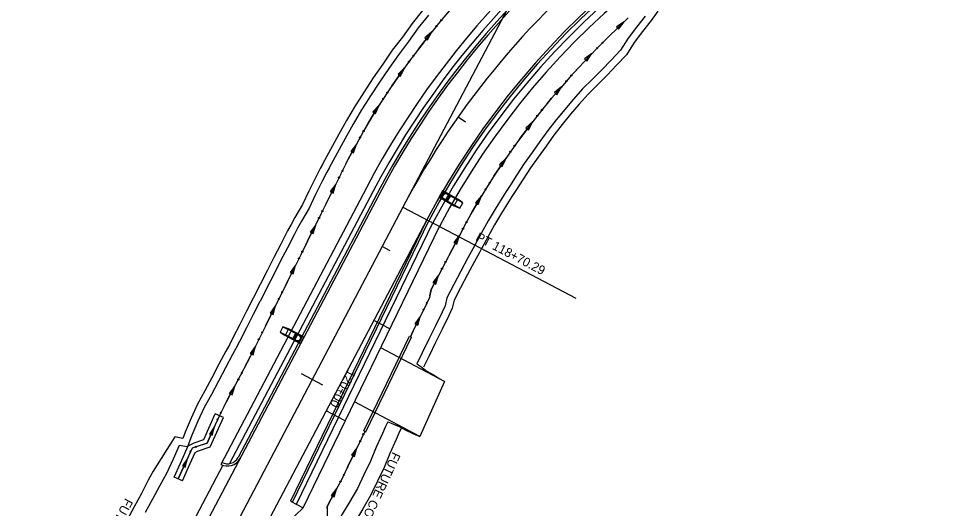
# Model space of a CAD drawing. Extents: x 979959 to 994833, y 1835619 to 1845316.
# Drawn here: x 981201 to 981821, y 1841316 to 1841642 of the extents above; entities that cross this region are included whole.
import ezdxf

# ---------------------------------------------------------------- set-up
doc = ezdxf.new("R2010")
doc.units = 0
for name, color, linetype in [('Future 5 Lane Construction Limits', 7, 'Continuous'), ('R_CONCRETE', 7, 'Continuous'), ('R_Drainage', 7, 'Continuous'), ('R_Horz Alg', 7, 'Continuous'), ('R_Horz Alg Annot', 7, 'Continuous'), ('R_Horz Alg Annot_Side Road', 7, 'Continuous'), ('R_Horz Alg Stationing', 7, 'Continuous'), ('R_Proposed Const Limits', 7, 'Continuous'), ('R_Proposed Road', 7, 'Continuous'), ('R_Special Ditch', 7, 'Continuous')]:
    doc.layers.add(name, color=color, linetype=linetype)

msp = doc.modelspace()

# ---------------------------------------------------------------- linework, layer by layer
at = {"layer": 'Future 5 Lane Construction Limits'}
for points in [[(981469.86, 1841647.75), (981462.95, 1841639.14), (981456.53, 1841630.08), (981449.82, 1841621.29), (981443.46, 1841612.11), (981437.18, 1841602.97), (981431.1, 1841593.69), (981427.88, 1841588.75), (981425.1, 1841584.24), (981419.39, 1841574.68), (981413.98, 1841564.96), (981408.66, 1841555.26), (981403.45, 1841545.52), (981403.29, 1841545.22), (981401.89, 1841542.58), (981398.76, 1841536.53), (981394.3, 1841527.52), (981389.96, 1841518.68), (981385.02, 1841510.12), (981382.41, 1841505.41), (981380.17, 1841501.16), (981375.65, 1841492.23), (981371, 1841483.4), (981366.42, 1841474.47), (981361.88, 1841465.54), (981361.75, 1841465.28), (981357.36, 1841456.61), (981357.25, 1841456.4), (981352.83, 1841447.7), (981348.31, 1841438.79), (981343.77, 1841429.91), (981341.36, 1841425.28), (981339.12, 1841421.19), (981334.29, 1841412.35), (981329.76, 1841403.44), (981324.98, 1841394.75), (981320.05, 1841385.8), (981315.89, 1841376.42), (981311.85, 1841367.11), (981310.28, 1841363.07)], [(981626.6, 1841647.41), (981622.05, 1841641.05), (981616.26, 1841633.71), (981610.88, 1841626.49), (981605.76, 1841618.26), (981599.17, 1841611.33), (981592.86, 1841604.77), (981586.39, 1841598.4), (981580.12, 1841592.15), (981574.3, 1841585.52), (981568.49, 1841578.71), (981562.83, 1841571.84), (981557.42, 1841564.81), (981552.17, 1841557.56), (981546.89, 1841550.27), (981541.71, 1841543.04), (981536.83, 1841535.61), (981532, 1841528.08), (981529.5, 1841524.06), (981527.25, 1841520.44), (981522.45, 1841512.89), (981517.94, 1841505.24), (981513.57, 1841497.48), (981509.32, 1841489.61), (981509.21, 1841489.4), (981507.81, 1841486.74), (981504.55, 1841480.83), (981499.91, 1841472.02), (981495.22, 1841463.2), (981490.94, 1841454.93), (981489.76, 1841449.64), (981487.46, 1841444.88), (981483.1, 1841435.84), (981478.66, 1841426.86), (981474.26, 1841417.9), (981470.68, 1841410.51)], [(981455.78, 1841369.76), (981454.2, 1841366.49), (981452.42, 1841362.24), (981448.28, 1841353.1), (981444.33, 1841343.79), (981439.95, 1841334.52), (981435.42, 1841325.11), (981430.15, 1841316.11), (981425.1, 1841307.51), (981420.98, 1841300.36)], [(981310.28, 1841363.07), (981304.97, 1841364.01), (981290.56, 1841341.24)], [(981290.56, 1841341.24), (981287.4, 1841335.32), (981282.82, 1841326.43), (981278.1, 1841317.62), (981273.33, 1841308.83)]]:
    msp.add_lwpolyline(points, dxfattribs=at)
at = {"layer": 'R_CONCRETE'}
for p, q in [((981337.43, 1841377), (981331.95, 1841379.45)), ((981310.1, 1841334.88), (981304.62, 1841337.34))]:
    msp.add_line(p, q, dxfattribs=at)
for points in [[(981304.62, 1841337.34), (981308.73, 1841346.48), (981313.95, 1841358.11), (981317.83, 1841360.17), (981324.28, 1841362.36), (981331.95, 1841379.45)], [(981310.1, 1841334.88), (981314.2, 1841344.02), (981318.58, 1841353.78), (981320.22, 1841354.65), (981328.68, 1841357.52), (981337.43, 1841377)]]:
    msp.add_lwpolyline(points, dxfattribs=at)
at = {"layer": 'R_Drainage'}
for p, q in [((981483.52, 1841527.9), (981481.03, 1841523.57)), ((981481.9, 1841523.07), (981484.39, 1841527.4)), ((981482.33, 1841522.82), (981484.82, 1841527.15)), ((981482.58, 1841523.25), (981484.58, 1841526.72)), ((981483.52, 1841527.9), (981493.49, 1841522.17)), ((981484.58, 1841526.72), (981493.25, 1841521.74)), ((981481.03, 1841523.57), (981482.33, 1841522.82)), ((981481.9, 1841523.07), (981491, 1841517.84)), ((981482.58, 1841523.25), (981491.25, 1841518.27)), ((981488.73, 1841524.91), (981486.23, 1841520.58)), ((981491.25, 1841518.27), (981493.25, 1841521.74)), ((981496.71, 1841519.74), (981493.25, 1841521.74)), ((981496.71, 1841519.74), (981493.49, 1841522.17)), ((981494.72, 1841516.28), (981496.71, 1841519.74)), ((981491, 1841517.84), (981494.72, 1841516.28)), ((981494.72, 1841516.28), (981491.25, 1841518.27)), ((981377.05, 1841437.28), (981375.19, 1841433.74)), ((981375.19, 1841433.74), (981378.5, 1841431.44)), ((981375.19, 1841433.74), (981378.73, 1841431.88)), ((981380.83, 1841435.86), (981377.05, 1841437.28)), ((981377.05, 1841437.28), (981380.59, 1841435.42)), ((981380.59, 1841435.42), (981378.73, 1841431.88)), ((981389.44, 1841430.76), (981380.59, 1841435.42)), ((981390.11, 1841430.97), (981380.83, 1841435.86)), ((981383.36, 1841428.87), (981385.69, 1841433.3)), ((981388.67, 1841426.08), (981378.49, 1841431.44)), ((981387.58, 1841427.22), (981378.73, 1841431.88)), ((981389.67, 1841431.2), (981387.34, 1841426.78)), ((981389.44, 1841430.76), (981387.58, 1841427.22)), ((981390.11, 1841430.97), (981387.78, 1841426.54)), ((981388.67, 1841426.08), (981391, 1841430.5)), ((981391, 1841430.5), (981389.67, 1841431.2)), ((981430.84, 1841368.02), (981461.27, 1841431.06)), ((981432.19, 1841367.36), (981462.62, 1841430.4)), ((981461.27, 1841431.06), (981462.62, 1841430.4)), ((981430.84, 1841368.02), (981432.19, 1841367.36))]:
    msp.add_line(p, q, dxfattribs=at)
for points in [[(981484.82, 1841527.15), (981482.33, 1841522.82), (981481.03, 1841523.57), (981483.52, 1841527.9)], [(981488.73, 1841524.91), (981486.23, 1841520.58), (981481.9, 1841523.07), (981484.39, 1841527.4)], [(981383.36, 1841428.87), (981385.69, 1841433.3), (981390.11, 1841430.97), (981387.78, 1841426.54)], [(981387.34, 1841426.78), (981389.67, 1841431.2), (981391, 1841430.5), (981388.67, 1841426.08)]]:
    msp.add_lwpolyline(points, close=True, dxfattribs=at)
for centre, radius in [((981485.31, 1841523.99), 2.5), ((981485.31, 1841523.99), 2.5), ((981485.31, 1841523.99), 2), ((981485.31, 1841523.99), 2), ((981386.74, 1841429.92), 2.5), ((981386.74, 1841429.92), 2.5), ((981386.74, 1841429.92), 2), ((981386.74, 1841429.92), 2)]:
    msp.add_circle(centre, radius, dxfattribs=at)
at = {"layer": 'R_Horz Alg'}
msp.add_line((981456.9, 1841516.96), (980717.33, 1840113.21), dxfattribs=at)
msp.add_arc((981939.67, 1841262.61), 545.67, 103.27832, 152.21752, dxfattribs=at)
at = {"layer": 'R_Horz Alg Annot'}
msp.add_lwpolyline([(981456.9, 1841516.96), (981571.91, 1841456.37)], dxfattribs=at)
at = {"layer": 'R_Horz Alg Annot_Side Road'}
msp.add_line((981572.65, 1841736.66), (981456.9, 1841516.96), dxfattribs=at)
at = {"layer": 'R_Horz Alg Stationing'}
for points in [[(981498.48, 1841573.42), (981493.57, 1841576.87)], [(981448.36, 1841487.88), (981443.05, 1841490.68)], [(981403.52, 1841398.48), (981389.36, 1841405.94)]]:
    msp.add_lwpolyline(points, dxfattribs=at)
at = {"layer": 'R_Proposed Const Limits'}
for points in [[(981487.65, 1841647.5), (981480.68, 1841639.14), (981473.86, 1841630.66), (981467.2, 1841622.06), (981460.7, 1841613.34), (981454.36, 1841604.5), (981448.18, 1841595.54), (981442.17, 1841586.48), (981439.06, 1841581.64), (981436.42, 1841577.24), (981430.95, 1841567.84), (981425.66, 1841558.34), (981420.54, 1841548.75), (981415.61, 1841539.08), (981415.46, 1841538.79), (981414.15, 1841536.14), (981411.15, 1841530.09), (981406.71, 1841521.13), (981402.27, 1841512.17), (981397.83, 1841503.2), (981395.48, 1841498.46), (981393.38, 1841494.24), (981388.94, 1841485.28), (981384.5, 1841476.32), (981380.06, 1841467.35), (981375.62, 1841458.39), (981375.49, 1841458.13), (981371.17, 1841449.43), (981371.07, 1841449.21), (981366.73, 1841440.47), (981362.29, 1841431.5), (981357.85, 1841422.54), (981355.5, 1841417.8), (981355.49, 1841417.79), (981353.31, 1841413.63), (981348.65, 1841404.78), (981344, 1841395.93), (981339.34, 1841387.08), (981334.69, 1841378.23), (981330.58, 1841369.09), (981326.48, 1841359.94), (981316.53, 1841356.52), (981307.36, 1841336.11)], [(981473.85, 1841644.74), (981466.95, 1841636.13), (981460.56, 1841627.11), (981453.86, 1841618.34), (981447.58, 1841609.27), (981441.33, 1841600.18), (981435.29, 1841590.96), (981432.1, 1841586.07), (981429.37, 1841581.65), (981423.72, 1841572.18), (981418.36, 1841562.54), (981413.06, 1841552.88), (981407.86, 1841543.16), (981407.71, 1841542.88), (981406.33, 1841540.26), (981403.22, 1841534.27), (981398.78, 1841525.31), (981394.38, 1841516.32), (981389.37, 1841507.66), (981386.81, 1841503.03), (981384.61, 1841498.86), (981380.1, 1841489.94), (981375.44, 1841481.09), (981370.88, 1841472.19), (981366.34, 1841463.28), (981366.21, 1841463.02), (981361.82, 1841454.36), (981361.71, 1841454.14), (981357.29, 1841445.44), (981352.77, 1841436.52), (981348.21, 1841427.61), (981345.77, 1841422.92), (981345.77, 1841422.91), (981343.51, 1841418.79), (981338.72, 1841410.01), (981334.18, 1841401.1), (981329.36, 1841392.34), (981324.53, 1841383.58), (981320.47, 1841374.42), (981316.48, 1841365.21), (981313.46, 1841357.43)], [(981618.05, 1841644.05), (981612.29, 1841636.75), (981606.74, 1841629.31), (981601.78, 1841621.34), (981595.56, 1841614.79), (981589.3, 1841608.28), (981582.88, 1841601.95), (981576.48, 1841595.58), (981570.52, 1841588.79), (981564.66, 1841581.92), (981558.92, 1841574.96), (981553.41, 1841567.81), (981548.12, 1841560.5), (981542.83, 1841553.2), (981537.58, 1841545.87), (981532.63, 1841538.34), (981527.77, 1841530.75), (981525.25, 1841526.7), (981523.01, 1841523.11), (981518.19, 1841515.5), (981513.61, 1841507.74), (981509.19, 1841499.89), (981504.91, 1841491.97), (981504.79, 1841491.73), (981503.41, 1841489.11), (981500.15, 1841483.2), (981495.49, 1841474.35), (981490.8, 1841465.53), (981486.2, 1841456.65), (981485.01, 1841451.29), (981482.96, 1841447.05), (981478.61, 1841438.04), (981474.17, 1841429.07), (981469.77, 1841420.09), (981466.18, 1841412.69)], [(981466.18, 1841412.69), (981468.78, 1841410.8), (981472.88, 1841407.84), (981477.18, 1841405.28), (981481.51, 1841402.77), (981484.58, 1841400.98)], [(981446.77, 1841374.11), (981445.08, 1841370.6), (981445.08, 1841370.59), (981443.25, 1841366.24), (981439.12, 1841357.12), (981435.2, 1841347.88), (981430.92, 1841338.83), (981426.59, 1841329.81), (981421.53, 1841321.17), (981416.45, 1841312.54), (981412.32, 1841305.35)], [(981446.77, 1841374.11), (981449.01, 1841373.27), (981454.85, 1841370.67), (981458.89, 1841368.62), (981463.53, 1841366.35), (981468.17, 1841364.42)], [(981313.46, 1841357.43), (981307.95, 1841358.4), (981303.88, 1841349.25)], [(981303.88, 1841349.25), (981299.71, 1841340.14), (981294.93, 1841331.35), (981290.21, 1841322.54), (981285.41, 1841313.76)]]:
    msp.add_lwpolyline(points, dxfattribs=at)
at = {"layer": 'R_Proposed Road'}
for p, q in [((981440.97, 1841525.35), (980701.4, 1840121.6)), ((981432.57, 1841529.78), (981335.62, 1841345.76)), ((981436.99, 1841527.45), (981341.56, 1841346.31)), ((981439.65, 1841526.05), (981347.12, 1841350.43)), ((981472.82, 1841508.57), (980733.25, 1840104.82)), ((981472.82, 1841508.57), (981382.06, 1841321.29)), ((981383.39, 1841320.59), (981474.15, 1841507.87)), ((981386.04, 1841319.19), (981476.8, 1841506.47)), ((981390.47, 1841316.86), (981481.23, 1841504.14)), ((981448.19, 1841435.98), (981437.53, 1841441.59)), ((981484.58, 1841400.98), (981442.08, 1841423.37)), ((981484.58, 1841400.99), (981468.17, 1841364.42)), ((981468.17, 1841364.42), (981424.63, 1841387.36)), ((981418.52, 1841374.75), (981405.84, 1841381.43)), ((981337, 1841345.16), (980694.33, 1840125.33)), ((981382.06, 1841321.29), (981390.47, 1841316.86)), ((981390.47, 1841316.86), (981371.29, 1841298.7))]:
    msp.add_line(p, q, dxfattribs=at)
for centre, radius, start, end in [((981939.67, 1841262.61), 527.67, 103.27832, 152.21752), ((981939.67, 1841262.61), 526.17, 103.27832, 152.21752), ((981939.67, 1841262.61), 573.17, 117.37429, 152.21752), ((981939.67, 1841262.61), 568.17, 117.37429, 152.21752), ((981939.67, 1841262.61), 523.17, 103.27832, 152.21752), ((981939.67, 1841262.61), 518.17, 103.27832, 152.21752), ((981939.67, 1841262.61), 565.17, 117.37429, 152.21752), ((981939.67, 1841262.61), 563.67, 117.37429, 152.21752), ((981340.04, 1841354.16), 9.5, 242.21752, 332.21752), ((981340.04, 1841354.16), 8, 242.21752, 332.21752)]:
    msp.add_arc(centre, radius, start, end, dxfattribs=at)
at = {"layer": 'R_Special Ditch'}
for p, q in [((981604.07, 1841640.24), (981598.98, 1841636.88)), ((981598.98, 1841636.88), (981600.43, 1841635.35)), ((981600.43, 1841635.35), (981604.07, 1841640.24)), ((981476.15, 1841633.51), (981471.57, 1841629.5)), ((981473.22, 1841628.17), (981476.15, 1841633.51)), ((981471.57, 1841629.5), (981473.22, 1841628.17)), ((981582.72, 1841619.11), (981577.79, 1841615.53)), ((981579.31, 1841614.06), (981582.72, 1841619.11)), ((981577.79, 1841615.53), (981579.31, 1841614.06)), ((981458, 1841609.58), (981453.65, 1841605.32)), ((981455.37, 1841604.09), (981458, 1841609.58)), ((981453.65, 1841605.32), (981455.37, 1841604.09)), ((981562.41, 1841596.99), (981557.7, 1841593.12)), ((981559.3, 1841591.74), (981562.41, 1841596.99)), ((981557.7, 1841593.12), (981559.3, 1841591.74)), ((981441.07, 1841584.77), (981436.94, 1841580.3)), ((981438.72, 1841579.15), (981441.07, 1841584.77)), ((981436.94, 1841580.3), (981438.72, 1841579.15)), ((981543.28, 1841573.83), (981538.78, 1841569.72)), ((981538.78, 1841569.72), (981540.46, 1841568.43)), ((981540.46, 1841568.43), (981543.28, 1841573.83)), ((981425.93, 1841558.84), (981422.17, 1841554.05)), ((981424.03, 1841553.05), (981425.93, 1841558.84)), ((981422.17, 1841554.05), (981424.03, 1841553.05)), ((981525.55, 1841549.59), (981521.28, 1841545.24)), ((981521.28, 1841545.24), (981523.03, 1841544.04)), ((981523.03, 1841544.04), (981525.55, 1841549.59)), ((981412.17, 1841532.14), (981408.56, 1841527.24)), ((981410.45, 1841526.3), (981412.17, 1841532.14)), ((981408.56, 1841527.24), (981410.45, 1841526.3)), ((981509.28, 1841524.34), (981505.26, 1841519.76)), ((981505.26, 1841519.76), (981507.07, 1841518.67)), ((981507.07, 1841518.67), (981509.28, 1841524.34)), ((981398.83, 1841505.23), (981395.22, 1841500.32)), ((981397.11, 1841499.38), (981398.83, 1841505.23)), ((981395.22, 1841500.32), (981397.11, 1841499.38)), ((981494.53, 1841498.18), (981490.82, 1841493.35)), ((981492.69, 1841492.37), (981494.53, 1841498.18)), ((981490.82, 1841493.35), (981492.69, 1841492.37)), ((981385.49, 1841478.31), (981381.88, 1841473.41)), ((981383.77, 1841472.47), (981385.49, 1841478.31)), ((981381.88, 1841473.41), (981383.77, 1841472.47)), ((981480.63, 1841471.56), (981476.91, 1841466.73)), ((981478.79, 1841465.75), (981480.63, 1841471.56)), ((981476.91, 1841466.73), (981478.79, 1841465.75)), ((981372.15, 1841451.4), (981368.54, 1841446.49)), ((981370.43, 1841445.55), (981372.15, 1841451.4)), ((981368.54, 1841446.49), (981370.43, 1841445.55)), ((981468.47, 1841444.24), (981464.91, 1841439.3)), ((981464.91, 1841439.3), (981466.81, 1841438.38)), ((981466.81, 1841438.38), (981468.47, 1841444.24)), ((981358.81, 1841424.49), (981355.2, 1841419.58)), ((981357.1, 1841418.64), (981358.81, 1841424.49)), ((981355.2, 1841419.58), (981357.1, 1841418.64)), ((981344.99, 1841397.82), (981341.26, 1841393)), ((981343.14, 1841392.02), (981344.99, 1841397.82)), ((981341.26, 1841393), (981343.14, 1841392.02)), ((981331.45, 1841371.02), (981328.03, 1841365.98)), ((981329.96, 1841365.11), (981331.45, 1841371.02)), ((981328.03, 1841365.98), (981329.96, 1841365.11)), ((981426.26, 1841356.79), (981422.7, 1841351.85)), ((981422.7, 1841351.85), (981424.6, 1841350.93)), ((981424.6, 1841350.93), (981426.26, 1841356.79)), ((981313.51, 1841349.79), (981310.08, 1841344.75)), ((981312.01, 1841343.89), (981313.51, 1841349.79)), ((981310.08, 1841344.75), (981312.01, 1841343.89)), ((981412.96, 1841329.86), (981409.18, 1841325.08)), ((981411.05, 1841324.08), (981412.96, 1841329.86)), ((981409.18, 1841325.08), (981411.05, 1841324.08))]:
    msp.add_line(p, q, dxfattribs=at)
for points in [[(981606.9, 1841642.91), (981600.17, 1841636.55), (981593.54, 1841630.09), (981587, 1841623.54), (981580.57, 1841616.89), (981574.25, 1841610.16), (981568.02, 1841603.32), (981561.9, 1841596.4), (981555.89, 1841589.39), (981549.99, 1841582.28), (981544.23, 1841575.06), (981538.6, 1841567.74), (981533.1, 1841560.32), (981527.75, 1841552.8), (981522.53, 1841545.18), (981517.45, 1841537.47), (981514.82, 1841533.35), (981512.51, 1841529.67), (981507.72, 1841521.78), (981503.08, 1841513.8), (981498.58, 1841505.74), (981494.23, 1841497.6), (981494.11, 1841497.36), (981492.74, 1841494.74), (981489.61, 1841488.76), (981484.98, 1841479.89), (981480.35, 1841471.03), (981475.72, 1841462.16), (981474.53, 1841456.81), (981472.49, 1841452.57), (981468.14, 1841443.56), (981463.79, 1841434.54), (981461.95, 1841430.73)], [(981593.27, 1841629.83), (981593.54, 1841630.09), (981600.17, 1841636.55), (981604.07, 1841640.24)], [(981466.92, 1841621.69), (981467.2, 1841622.06), (981473.86, 1841630.66), (981476.15, 1841633.51)], [(981593.24, 1841629.8), (981593.27, 1841629.83)], [(981466.9, 1841621.66), (981466.92, 1841621.69)], [(981572.45, 1841608.18), (981574.25, 1841610.16), (981580.57, 1841616.89), (981582.72, 1841619.11)], [(981449.39, 1841597.3), (981454.36, 1841604.5), (981458, 1841609.58)], [(981572.42, 1841608.15), (981572.45, 1841608.18)], [(981449.37, 1841597.27), (981449.39, 1841597.3)], [(981552.7, 1841585.55), (981555.89, 1841589.39), (981561.9, 1841596.4), (981562.41, 1841596.98)], [(981433.33, 1841571.93), (981436.42, 1841577.24), (981439.06, 1841581.64), (981441.07, 1841584.77)], [(981552.68, 1841585.52), (981552.7, 1841585.55)], [(981433.31, 1841571.9), (981433.33, 1841571.93)], [(981534.24, 1841561.86), (981538.6, 1841567.74), (981543.28, 1841573.83)], [(981418.92, 1841545.58), (981420.54, 1841548.75), (981425.66, 1841558.34), (981425.93, 1841558.84)], [(981534.22, 1841561.83), (981534.24, 1841561.86)], [(981418.9, 1841545.54), (981418.92, 1841545.58)], [(981517.22, 1841537.11), (981517.45, 1841537.47), (981522.53, 1841545.18), (981525.55, 1841549.59)], [(981405.51, 1841518.7), (981406.71, 1841521.13), (981411.15, 1841530.09), (981412.17, 1841532.14)], [(981517.2, 1841537.08), (981517.22, 1841537.11)], [(981501.73, 1841511.38), (981503.08, 1841513.8), (981507.72, 1841521.78), (981509.28, 1841524.34)], [(981405.49, 1841518.67), (981405.51, 1841518.7)], [(981501.71, 1841511.35), (981501.73, 1841511.38)], [(981392.17, 1841491.79), (981393.38, 1841494.24), (981395.48, 1841498.46), (981397.83, 1841503.2), (981398.83, 1841505.23)], [(981487.59, 1841484.88), (981489.61, 1841488.76), (981492.74, 1841494.74), (981494.11, 1841497.36), (981494.23, 1841497.6), (981494.54, 1841498.18)], [(981392.15, 1841491.75), (981392.17, 1841491.79)], [(981487.57, 1841484.85), (981487.59, 1841484.88)], [(981378.83, 1841464.87), (981380.06, 1841467.35), (981384.5, 1841476.32), (981385.49, 1841478.31)], [(981474.77, 1841457.86), (981475.72, 1841462.16), (981480.35, 1841471.03), (981480.63, 1841471.56)], [(981378.81, 1841464.84), (981378.83, 1841464.87)], [(981474.76, 1841457.83), (981474.77, 1841457.86)], [(981365.49, 1841437.96), (981366.73, 1841440.47), (981371.07, 1841449.21), (981371.17, 1841449.43), (981372.15, 1841451.4)], [(981461.95, 1841430.73), (981463.79, 1841434.54), (981468.14, 1841443.56), (981468.47, 1841444.24)], [(981365.47, 1841437.93), (981365.49, 1841437.96)], [(981351.99, 1841411.13), (981353.31, 1841413.63), (981355.49, 1841417.79), (981355.5, 1841417.8), (981357.85, 1841422.54), (981358.81, 1841424.49)], [(981351.97, 1841411.09), (981351.99, 1841411.13)], [(981338.01, 1841384.54), (981339.34, 1841387.08), (981344, 1841395.93), (981344.99, 1841397.82)], [(981337.99, 1841384.51), (981338.01, 1841384.54)], [(981323.77, 1841359.01), (981326.48, 1841359.94), (981330.58, 1841369.09), (981331.45, 1841371.02)], [(981431.52, 1841367.69), (981428.99, 1841362.45), (981424.64, 1841353.44), (981420.29, 1841344.43), (981415.94, 1841335.42), (981411.21, 1841326.61), (981406.47, 1841317.8), (981406.39, 1841308.47), (981393.02, 1841290.98)], [(981323.74, 1841359), (981323.77, 1841359.01)], [(981316.27, 1841355.94), (981315.57, 1841354.39), (981311.47, 1841345.25)], [(981419.74, 1841343.28), (981420.29, 1841344.43), (981424.64, 1841353.44), (981426.26, 1841356.79)], [(981307.36, 1841336.11), (981313.51, 1841349.79)], [(981419.72, 1841343.25), (981419.74, 1841343.28)], [(981406.46, 1841316.49), (981406.47, 1841317.8), (981411.21, 1841326.61), (981412.96, 1841329.86)]]:
    msp.add_lwpolyline(points, dxfattribs=at)
for centre in [(981479.26, 1841637.44), (981482.44, 1841641.31), (981589.7, 1841626.3), (981463.89, 1841617.68), (981586.17, 1841622.73), (981460.9, 1841613.67), (981565.7, 1841600.75), (981569.04, 1841604.49), (981446.55, 1841593.16), (981443.79, 1841588.98), (981549.48, 1841581.7), (981546.35, 1841577.78), (981428.34, 1841563.23), (981430.78, 1841567.6), (981531.27, 1841557.81), (981528.36, 1841553.73), (981416.61, 1841541.12), (981414.36, 1841536.64), (981514.49, 1841532.9), (981511.85, 1841528.64), (981403.24, 1841514.22), (981401.02, 1841509.73), (981499.25, 1841507.02), (981496.87, 1841502.61), (981387.68, 1841482.82), (981389.91, 1841487.3), (981482.91, 1841476.01), (981485.23, 1841480.45), (981376.57, 1841460.39), (981374.34, 1841455.9), (981472.79, 1841453.27), (981470.61, 1841448.76), (981363.23, 1841433.48), (981361, 1841428.99), (981347.29, 1841402.27), (981349.62, 1841406.7), (981335.64, 1841380.11), (981333.47, 1841375.6), (981430.58, 1841365.83), (981428.4, 1841361.31), (981315.52, 1841354.37), (981319.01, 1841357.41), (981415.3, 1841334.29), (981417.52, 1841338.77)]:
    msp.add_circle(centre, 0.375, dxfattribs=at)

# ---------------------------------------------------------------- texts
at = {"layer": 'Future 5 Lane Construction Limits'}
for rotation, p in [(245.06874, (981450.11, 1841354.43)), (241.83177, (981272.19, 1841323.65))]:
    msp.add_text('FUTURE CONSTRUCTION LIMITS', height=6, rotation=rotation, dxfattribs=at).set_placement(p)
at = {"layer": 'R_Horz Alg Annot'}
msp.add_text('PT 118+70.29', height=6, rotation=332.21752, dxfattribs=at).set_placement((981504.81, 1841495.11))
at = {"layer": 'R_Horz Alg Stationing'}
msp.add_text('120+00', height=6, rotation=242.21752, dxfattribs=at).set_placement((981420.59, 1841409.43))

doc.saveas('drawing.dxf')
